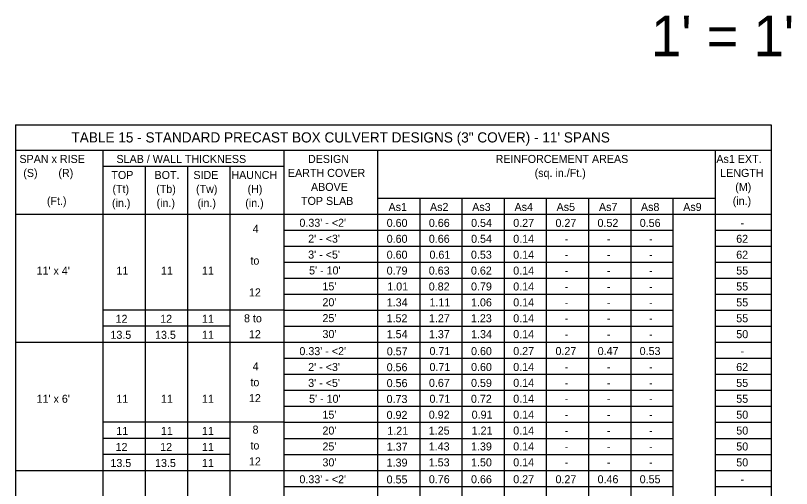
# Model space of a CAD drawing. Extents: x 10351.18 to 10353.4, y 76371.55 to 76372.62.
# Drawn here: x 10351.832 to 10352.443, y 76372.249 to 76372.621 of the extents above; entities that cross this region are included whole.
import ezdxf

# ---------------------------------------------------------------- set-up
doc = ezdxf.new("R2010")
doc.units = 0
doc.layers.add('AdhocPoint_dp', color=7, linetype='Continuous')
doc.layers.add('PlotBorder_dp', color=7, linetype='Continuous')

msp = doc.modelspace()

# ---------------------------------------------------------------- linework, layer by layer
at = {"layer": 'PlotBorder_dp'}
for p, q in [((10351.83244, 76372.53475), (10351.83244, 76371.96053)), ((10351.83244, 76372.53475), (10352.42718, 76372.53475)), ((10352.42718, 76372.53475), (10352.42718, 76371.96053)), ((10351.83244, 76372.51488), (10352.42718, 76372.51488)), ((10351.90108, 76372.51488), (10351.90108, 76371.96053)), ((10352.04352, 76372.51488), (10352.04352, 76371.96053)), ((10352.1174, 76372.51488), (10352.1174, 76371.96053)), ((10352.38299, 76372.51488), (10352.38299, 76371.96053)), ((10351.90108, 76372.50228), (10352.04352, 76372.50228)), ((10351.93444, 76372.50228), (10351.93444, 76371.96053)), ((10351.9678, 76372.50228), (10351.9678, 76371.96053)), ((10352.00116, 76372.50228), (10352.00116, 76371.96053)), ((10352.1174, 76372.47713), (10352.38299, 76372.47713)), ((10352.1506, 76372.47713), (10352.1506, 76371.96053)), ((10352.1838, 76372.47713), (10352.1838, 76371.96053)), ((10352.217, 76372.47713), (10352.217, 76371.96053)), ((10352.2502, 76372.47713), (10352.2502, 76371.96053)), ((10352.28339, 76372.47713), (10352.28339, 76371.96053)), ((10352.28339, 76372.47713), (10352.28339, 76371.96053)), ((10352.31659, 76372.47713), (10352.31659, 76371.96053)), ((10352.34979, 76372.47713), (10352.34979, 76371.96053)), ((10351.83244, 76372.46453), (10352.42718, 76372.46453)), ((10352.04352, 76372.45193), (10352.34979, 76372.45193)), ((10352.38299, 76372.45192), (10352.42718, 76372.45192)), ((10352.04352, 76372.43933), (10352.34979, 76372.43933)), ((10352.38299, 76372.43932), (10352.42718, 76372.43932)), ((10352.04352, 76372.42673), (10352.34979, 76372.42673)), ((10352.38299, 76372.42672), (10352.42718, 76372.42672)), ((10352.04352, 76372.41413), (10352.34979, 76372.41413)), ((10352.38299, 76372.41412), (10352.42718, 76372.41412)), ((10352.04352, 76372.40153), (10352.34979, 76372.40153)), ((10352.38299, 76372.40152), (10352.42718, 76372.40152)), ((10352.04352, 76372.38893), (10351.90108, 76372.38893)), ((10352.04352, 76372.38893), (10352.34979, 76372.38893)), ((10352.38299, 76372.38892), (10352.42718, 76372.38892)), ((10352.00116, 76372.37633), (10351.90108, 76372.37633)), ((10352.04352, 76372.37633), (10352.34979, 76372.37633)), ((10352.38299, 76372.37632), (10352.42718, 76372.37632)), ((10351.83244, 76372.36373), (10352.34979, 76372.36373)), ((10352.38299, 76372.36372), (10352.42718, 76372.36372)), ((10352.04352, 76372.35113), (10352.34979, 76372.35113)), ((10352.38299, 76372.35112), (10352.42718, 76372.35112)), ((10352.04352, 76372.33853), (10352.34979, 76372.33853)), ((10352.38299, 76372.33852), (10352.42718, 76372.33852)), ((10352.04352, 76372.32593), (10352.34979, 76372.32593)), ((10352.38299, 76372.32592), (10352.42718, 76372.32592)), ((10352.04352, 76372.31333), (10352.34979, 76372.31333)), ((10352.38299, 76372.31332), (10352.42718, 76372.31332)), ((10352.04352, 76372.30073), (10351.90108, 76372.30073)), ((10352.04352, 76372.30073), (10352.34979, 76372.30073)), ((10352.38299, 76372.30072), (10352.42718, 76372.30072)), ((10352.00116, 76372.28813), (10351.90108, 76372.28813)), ((10352.04352, 76372.28813), (10352.34979, 76372.28813)), ((10352.38299, 76372.28812), (10352.42718, 76372.28812)), ((10352.00116, 76372.27553), (10351.90108, 76372.27553)), ((10352.04352, 76372.27553), (10352.34979, 76372.27553)), ((10352.38299, 76372.27552), (10352.42718, 76372.27552)), ((10351.83244, 76372.26293), (10352.34979, 76372.26293)), ((10352.04414, 76372.26292), (10352.11631, 76372.26292)), ((10352.38299, 76372.26292), (10352.42718, 76372.26292)), ((10352.04352, 76372.25033), (10352.34979, 76372.25033)), ((10352.38299, 76372.25032), (10352.42718, 76372.25032))]:
    msp.add_line(p, q, dxfattribs=at)

# ---------------------------------------------------------------- texts
at = {"layer": 'AdhocPoint_dp'}
for s, height, p in [("1' = 1'", 0.032, (10352.33259, 76372.58867)), ('TABLE 15 - STANDARD PRECAST BOX CULVERT DESIGNS (3" COVER) - 11\' SPANS', 0.008, (10351.87646, 76372.52082)), ('SLAB / WALL THICKNESS', 0.0063, (10351.9119, 76372.50472)), ('As1', 0.0063, (10352.12602, 76372.46696)), ('As2', 0.0063, (10352.15865, 76372.46696)), ('As3', 0.0063, (10352.19185, 76372.46696)), ('As4', 0.0063, (10352.22517, 76372.46696)), ('As5', 0.0063, (10352.25827, 76372.46696)), ('As7', 0.0063, (10352.29162, 76372.46696)), ('As8', 0.0063, (10352.32466, 76372.46696)), ('As9', 0.0063, (10352.35791, 76372.46696)), ("11' x 4'", 0.0063, (10351.84902, 76372.41686)), ('11', 0.0063, (10351.91184, 76372.41686)), ('11', 0.0063, (10351.94693, 76372.41686)), ('11', 0.0063, (10351.97917, 76372.41686)), ('12', 0.0063, (10351.91119, 76372.37899)), ('12', 0.0063, (10351.94628, 76372.37899)), ('11', 0.0063, (10351.97914, 76372.37899)), ('13.5', 0.0063, (10351.90714, 76372.36639)), ('13.5', 0.0063, (10351.94224, 76372.36639)), ('11', 0.0063, (10351.97914, 76372.36639)), ('11', 0.0063, (10351.91176, 76372.29079)), ('11', 0.0063, (10351.94685, 76372.29079)), ('11', 0.0063, (10351.97914, 76372.29079)), ('12', 0.0063, (10351.91119, 76372.27819)), ('12', 0.0063, (10351.94628, 76372.27819)), ('11', 0.0063, (10351.97914, 76372.27819)), ('13.5', 0.0063, (10351.90714, 76372.26559)), ('13.5', 0.0063, (10351.94224, 76372.26559)), ('11', 0.0063, (10351.97914, 76372.26559))]:
    msp.add_text(s, height=height, dxfattribs=at).set_placement(p)
at = {"layer": 'PlotBorder_dp'}
for s, p in [('SPAN x RISE', (10351.83553, 76372.50472)), ('DESIGN', (10352.06262, 76372.50472)), ('REINFORCEMENT AREAS', (10352.2103, 76372.50472)), ('(S)       (R)', (10351.83857, 76372.49372)), ('(sq. in./Ft.)', (10352.241, 76372.49372)), ('TOP', (10351.9079, 76372.49212)), ('BOT.', (10351.94183, 76372.49212)), ('SIDE', (10351.97243, 76372.49212)), ('HAUNCH', (10352.00232, 76372.49212)), ('EARTH COVER', (10352.04683, 76372.49372)), ('ABOVE', (10352.06497, 76372.48272)), ('(Tt)', (10351.90875, 76372.48112)), ('(Tb)', (10351.94317, 76372.48112)), ('(Tw)', (10351.97453, 76372.48112)), ('(H)', (10352.01506, 76372.48112)), ('(Ft.)', (10351.85715, 76372.47172)), ('(in.)', (10351.90836, 76372.47012)), ('(in.)', (10351.94345, 76372.47012)), ('(in.)', (10351.97568, 76372.47012)), ('(in.)', (10352.01325, 76372.47012)), ('TOP SLAB', (10352.05714, 76372.47172)), ("0.33' - <2'", (10352.05588, 76372.45452)), ('0.60', (10352.12456, 76372.45441)), ('0.66', (10352.15774, 76372.45441)), ('0.54', (10352.191, 76372.45441)), ('0.27', (10352.22418, 76372.45441)), ('0.27', (10352.25741, 76372.45441)), ('0.52', (10352.29048, 76372.45441)), ('0.56', (10352.32372, 76372.45441)), ('4', (10352.0191, 76372.44976)), ("2' - <3'", (10352.06278, 76372.44202)), ('0.60', (10352.12456, 76372.44191)), ('0.66', (10352.15774, 76372.44191)), ('0.54', (10352.191, 76372.44191)), ('0.14', (10352.22416, 76372.44191)), ('-', (10352.26467, 76372.44191)), ('-', (10352.29788, 76372.44191)), ('-', (10352.33106, 76372.44191)), ("3' - <5'", (10352.06278, 76372.42952)), ('0.60', (10352.12456, 76372.42941)), ('0.61', (10352.15824, 76372.42941)), ('0.53', (10352.19087, 76372.42941)), ('0.14', (10352.22416, 76372.42941)), ('to', (10352.01732, 76372.42476)), ('-', (10352.26467, 76372.42941)), ('-', (10352.29788, 76372.42941)), ('-', (10352.33106, 76372.42941)), ("5' - 10'", (10352.06349, 76372.41702)), ('0.79', (10352.12454, 76372.41691)), ('0.63', (10352.15767, 76372.41691)), ('0.62', (10352.19088, 76372.41691)), ('0.14', (10352.22416, 76372.41691)), ('-', (10352.26467, 76372.41691)), ('-', (10352.29788, 76372.41691)), ('-', (10352.33106, 76372.41691)), ("15'", (10352.07401, 76372.40452)), ('1.01', (10352.12504, 76372.40441)), ('0.82', (10352.15768, 76372.40441)), ('0.79', (10352.19094, 76372.40441)), ('0.14', (10352.22416, 76372.40441)), ('12', (10352.01615, 76372.39976)), ('-', (10352.26467, 76372.40441)), ('-', (10352.29788, 76372.40441)), ('-', (10352.33106, 76372.40441)), ("20'", (10352.07401, 76372.39202)), ('1.34', (10352.1246, 76372.39191)), ('1.11', (10352.15824, 76372.39191)), ('1.06', (10352.19094, 76372.39191)), ('0.14', (10352.22416, 76372.39191)), ('-', (10352.26467, 76372.39191)), ('-', (10352.29788, 76372.39191)), ('-', (10352.33106, 76372.39191)), ('8 to', (10352.01228, 76372.37939)), ("25'", (10352.07401, 76372.37952)), ('1.52', (10352.12448, 76372.37941)), ('1.27', (10352.15782, 76372.37941)), ('1.23', (10352.19087, 76372.37941)), ('0.14', (10352.22416, 76372.37941)), ('-', (10352.26467, 76372.37941)), ('-', (10352.29788, 76372.37941)), ('-', (10352.33106, 76372.37941)), ('12', (10352.01615, 76372.36689)), ("30'", (10352.07401, 76372.36702)), ('1.54', (10352.1246, 76372.36691)), ('1.37', (10352.15782, 76372.36691)), ('1.34', (10352.191, 76372.36691)), ('0.14', (10352.22416, 76372.36691)), ('-', (10352.26467, 76372.36691)), ('-', (10352.29788, 76372.36691)), ('-', (10352.33106, 76372.36691)), ("0.33' - <2'", (10352.05588, 76372.35358)), ('0.71', (10352.15824, 76372.35358)), ('0.60', (10352.19096, 76372.35358)), ('0.27', (10352.22418, 76372.35363)), ('0.27', (10352.25741, 76372.35363)), ('0.47', (10352.29062, 76372.35363)), ('0.53', (10352.32365, 76372.35363)), ('0.57', (10352.12462, 76372.35342)), ('-', (10352.40298, 76372.35358)), ('4', (10352.0191, 76372.34158)), ("2' - <3'", (10352.06278, 76372.34108)), ('0.56', (10352.12454, 76372.34092)), ('0.71', (10352.15824, 76372.34108)), ('0.60', (10352.19096, 76372.34108)), ('0.14', (10352.22416, 76372.34113)), ('-', (10352.26467, 76372.34113)), ('-', (10352.29788, 76372.34113)), ('-', (10352.33106, 76372.34113)), ('62', (10352.39964, 76372.34108)), ('to', (10352.01732, 76372.32908)), ("3' - <5'", (10352.06278, 76372.32858)), ('0.56', (10352.12454, 76372.32842)), ('0.67', (10352.15782, 76372.32858)), ('0.59', (10352.19094, 76372.32858)), ('0.14', (10352.22416, 76372.32863)), ('-', (10352.26467, 76372.32863)), ('-', (10352.29788, 76372.32863)), ('-', (10352.33106, 76372.32863)), ('55', (10352.39967, 76372.32858)), ("11' x 6'", (10351.84905, 76372.31608)), ('11', (10351.91182, 76372.31608)), ('11', (10351.94691, 76372.31608)), ('11', (10351.97915, 76372.31608)), ('12', (10352.01615, 76372.31658)), ("5' - 10'", (10352.06349, 76372.31608)), ('0.73', (10352.12447, 76372.31592)), ('0.71', (10352.15824, 76372.31608)), ('0.72', (10352.19088, 76372.31608)), ('0.14', (10352.22416, 76372.31613)), ('-', (10352.26467, 76372.31613)), ('-', (10352.29788, 76372.31613)), ('-', (10352.33106, 76372.31613)), ('55', (10352.39967, 76372.31608)), ("15'", (10352.07401, 76372.30358)), ('0.92', (10352.12448, 76372.30342)), ('0.92', (10352.15768, 76372.30358)), ('0.91', (10352.19144, 76372.30358)), ('0.14', (10352.22416, 76372.30363)), ('-', (10352.26467, 76372.30363)), ('-', (10352.29788, 76372.30363)), ('-', (10352.33106, 76372.30363)), ('50', (10352.39972, 76372.30358)), ('8', (10352.01899, 76372.29186)), ("20'", (10352.07401, 76372.29108)), ('1.21', (10352.12504, 76372.29092)), ('1.25', (10352.1577, 76372.29108)), ('1.21', (10352.19144, 76372.29108)), ('0.14', (10352.22416, 76372.29113)), ('-', (10352.26467, 76372.29113)), ('-', (10352.29788, 76372.29113)), ('-', (10352.33106, 76372.29113)), ('50', (10352.39972, 76372.29108)), ('to', (10352.01732, 76372.27936)), ("25'", (10352.07401, 76372.27858)), ('1.37', (10352.12462, 76372.27842)), ('1.43', (10352.15767, 76372.27858)), ('1.39', (10352.19094, 76372.27858)), ('0.14', (10352.22416, 76372.27863)), ('-', (10352.26467, 76372.27863)), ('-', (10352.29788, 76372.27863)), ('-', (10352.33106, 76372.27863)), ('50', (10352.39972, 76372.27858)), ('12', (10352.01615, 76372.26686)), ("30'", (10352.07401, 76372.26608)), ('1.39', (10352.12454, 76372.26592)), ('1.53', (10352.15767, 76372.26608)), ('1.50', (10352.19096, 76372.26608)), ('0.14', (10352.22416, 76372.26613)), ('-', (10352.26467, 76372.26613)), ('-', (10352.29788, 76372.26613)), ('-', (10352.33106, 76372.26613)), ('50', (10352.39972, 76372.26608)), ("0.33' - <2'", (10352.05588, 76372.2528)), ('0.55', (10352.1245, 76372.25264)), ('0.76', (10352.15774, 76372.2528)), ('0.66', (10352.19094, 76372.2528)), ('0.27', (10352.22418, 76372.2528)), ('0.27', (10352.25741, 76372.2528)), ('0.46', (10352.29054, 76372.2528)), ('0.55', (10352.32368, 76372.2528)), ('-', (10352.40298, 76372.2528))]:
    msp.add_text(s, height=0.0063, dxfattribs=at).set_placement(p)
for s, p in [('As1 EXT.', (10352.38404, 76372.50472)), ('LENGTH', (10352.38706, 76372.49372)), ('(M)', (10352.39887, 76372.48272)), ('(in.)', (10352.39691, 76372.47172)), ('-', (10352.40298, 76372.45441)), ('62', (10352.39964, 76372.44191)), ('62', (10352.39964, 76372.42941)), ('55', (10352.39967, 76372.41691)), ('55', (10352.39967, 76372.40441)), ('55', (10352.39967, 76372.39191)), ('55', (10352.39967, 76372.37941)), ('50', (10352.39972, 76372.36691))]:
    msp.add_text(s, height=0.0063, rotation=360, dxfattribs=at).set_placement(p)

doc.saveas('drawing.dxf')
